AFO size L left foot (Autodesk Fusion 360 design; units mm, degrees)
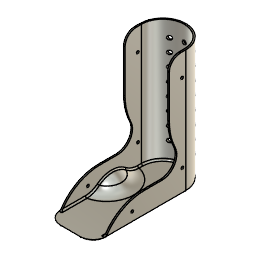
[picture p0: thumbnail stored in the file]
part number: 2025-10-02-12-56-12-317
sketch "Sketch1" plane through (0, 0, 0) normal (0, 0, 1) x axis (1, 0, 0)
  line L1 (-30.6, -123.83) -> (-30.6, 0)
  line L2 (30.6, -123.83) -> (-30.6, -123.83)
  line L3 (30.6, 0) -> (30.6, -123.83)
  line L4 (-28.6, 0) -> (-28.6, -123.83)
  line L5 (28.6, 0) -> (28.6, -123.83)
  line L6 (-28.6, 0) -> (-30.6, 0)
  line L7 (30.6, 0) -> (28.6, 0)
  line L8 (-28.6, -106.33) -> (-30.6, -106.33)
  line L9 (-13.1, -123.83) -> (-13.1, -106.33)
  line L10 (13.1, -123.83) -> (13.1, -106.33)
  line L11 (13.1, -123.83) -> (-13.1, -123.83)
  line L12 (42, -106.33) -> (-13.1252, -106.33)
  circle C1 centre (0, 0) radius 30.6
  circle C2 centre (0, 0) radius 28.6
  circle C3 centre (-13.1, -106.33) radius 17.5
  circle C4 centre (13.1, -106.33) radius 17.5
  circle C5 centre (-13.1, -106.33) radius 15.5
  circle C6 centre (13.1, -106.33) radius 15.5
  point P1 (0, 0)
  point P2 (0, 0)
  point P3 (-30.6, 0)
  point P6 (30.6, 0)
  point P7 (0, 0)
  point P8 (-28.6, 0)
  point P10 (28.6, 0)
  point P11 (28.6, -123.83)
  point P9 (-28.6, -123.83)
  point P16 (-30.6, -106.33)
  point P17 (-28.6, -106.33)
  point P12 (-13.1, -106.33)
  point P18 (-13.1, -106.33)
  point P19 (-13.1, -123.83)
  point P15 (13.1, -106.33)
  point P20 (13.1, -106.33)
  point P21 (13.1, -123.83)
  point P14 (-13.1, -106.33)
  coincident P1 P2
  coincident C1 P3
  tangent C1 L1
  vertical L1
  perpendicular L1 L2
  coincident C1 P6
  tangent C1 L3
  perpendicular L2 L3
  coincident P1 P7
  vertical L4
  coincident C2 P8
  vertical L5
  coincident C2 P10
  perpendicular L4 L6
  perpendicular L3 L7
  coincident L2 P11
  coincident L2 P9
  tangent L3 C4
  tangent L1 C3
  tangent L2 C3
  tangent L2 C4
  concentric C3 C5
  tangent L4 C5
  concentric C4 C6
  tangent L5 C6
  coincident C3 P16
  coincident C5 P17
  coincident L4 P17
  perpendicular L4 L8
  coincident P12 P18
  coincident L2 P19
  coincident C3 P19
  perpendicular L2 L9
  coincident P15 P20
  coincident L2 P21
  coincident C4 P21
  perpendicular L2 L10
  perpendicular L3 L12
  coincident P14 L12
  dimension "d2" diameter C1 = 61.2 (= "d57 + ( 2 * 2 ) * 1 mm")
  dimension "d4" distance P2 L2 = 123.83
  dimension "d57" diameter C2 = 57.2
  dimension "d73" diameter C3 = 35
  dimension "d74" diameter C4 = 35
extrude "Extrude1" new body sketch "Sketch1" profile of C1 L1 L3 L4 L5 L6 L7 C3 C4 L8 L12 along normal blind 30
extrude "Extrude2" add sketch "Sketch1" profile of C1 C2 L4 L5 C3 C4 C5 C6 L8 L9 L10 L12 along normal blind 2
extrude "Extrude8" add sketch "Sketch1" profile of L2 C3 C4 L11 along normal blind 2
extrude "Extrude3" add sketch "Sketch1" profile of C1 C2 L6 L7 along normal blind 165.1
work_plane "WorkPlane3" AlongDistance 40
sphere_primitive "SpherePrimitive3" Diameter 55
move_face "MoveFace3"
boundary_fill "BoundaryFill2"
offset_faces "OffsetFaces3" distance 2
shell "Shell5" innerThickness 2
mirror "Mirror2" mirrorStitchTolerance 0.1
extrude "Extrude16" cut of existing geometry blind -25
delete_face "DeleteFace1"
delete_face "DeleteFace2"
fillet "Fillet31" radius 25
work_plane "WorkPlane1" RotateAngle -90
sketch "Sketch2" plane through (30.6, 0, 0) normal (1, 0, 0) x axis (0, 1, 0)
  line L1 (0, 165.1) -> (-22, 165.1)
  line L2 (0, 30) -> (0, 165.1)
  line L3 (-22, 75.1) -> (-22, 165.1)
  line L4 (0, 30) -> (-22, 75.1)
  circle C1 centre (-5, 135.1) radius 1.75
  point P2 (0, 30)
  point P6 (0, 30)
  point P4 (0, 165.1)
  point P7 (0, 165.1)
  point P3 (-22, 165.1)
  point P5 (-22, 75.1)
  point P8 (-5, 135.1)
  horizontal L1
  perpendicular L1 L2
  perpendicular L1 L3
  coincident P2 P6
  coincident P4 P7
  dimension "d25" distance P3 P4 = 22
  dimension "d28" distance P3 P5 = 90
  dimension "d43" diameter C1 = 3.5
  dimension "d45" distance L3 P8 = 17
  dimension "d47" distance L1 P8 = 30
extrude "Extrude11" add sketch "Sketch2" against normal blind 2
mirror "Mirror1" mirrorStitchTolerance 0.1
work_plane "WorkPlane4" AlongDistance 24.25
sketch "Sketch9" plane through (0, 24.25, 0) normal (0, 1, 0) x axis (1, 0, 0)
  circle C1 centre (0, -25) radius 2.5
  circle C2 centre (0, -42) radius 2.5
  circle C3 centre (0, -59) radius 2.5
  circle C4 centre (0, -76) radius 2.5
  circle C5 centre (0, -110) radius 2.5
  circle C6 centre (0, -93) radius 2.5
  circle C7 centre (0, -144) radius 2.5
  circle C8 centre (0, -127) radius 2.5
  point P2 (0, -25)
  point P8 (0, 0)
  point P3 (0, -42)
  point P4 (0, -59)
  point P5 (0, -76)
  point P7 (0, -93)
  point P6 (0, -110)
  point P10 (0, -127)
  point P9 (0, -144)
  dimension "d123" diameter C1 = 5
  dimension "d124" diameter C2 = 5
  dimension "d125" diameter C3 = 5
  dimension "d126" diameter C4 = 5
  dimension "d127" diameter C5 = 5
  dimension "d128" diameter C6 = 5
  dimension "d129" distance P2 P8 = 25
  dimension "d130" distance P2 P3 = 17
  dimension "d131" distance P3 P4 = 17
  dimension "d132" distance P4 P5 = 17 (= "d131")
  dimension "d133" distance P5 P7 = 17 (= "d131")
  dimension "d134" distance P6 P7 = 17 (= "d131")
  dimension "d183" diameter C7 = 5
  dimension "d184" diameter C8 = 5
  dimension "d250" distance P6 P10 = 17
  dimension "d251" distance P9 P10 = 17
extrude "Extrude12" cut sketch "Sketch9" along normal blind 70
path_pattern "PathPattern2" PathPatternDelta 86
fillet "Fillet28" radius 60
fillet "Fillet18" radius 80
fillet "Fillet34" radius 20
fillet "Fillet35" radius 15
fillet "Fillet36" radius 2
fillet "Fillet37" radius 4
hole "Hole3" HoleDepth 90 HoleDiameter 3.5 TipAngle 118
hole "Hole4" HoleDepth 90 HoleDiameter 3.5 TipAngle 118
fillet "Fillet46" radius 10
fillet "Fillet47" radius 10
fillet "Fillet48" radius 2
fillet "Fillet49" radius 2
fillet "Fillet50" radius 10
